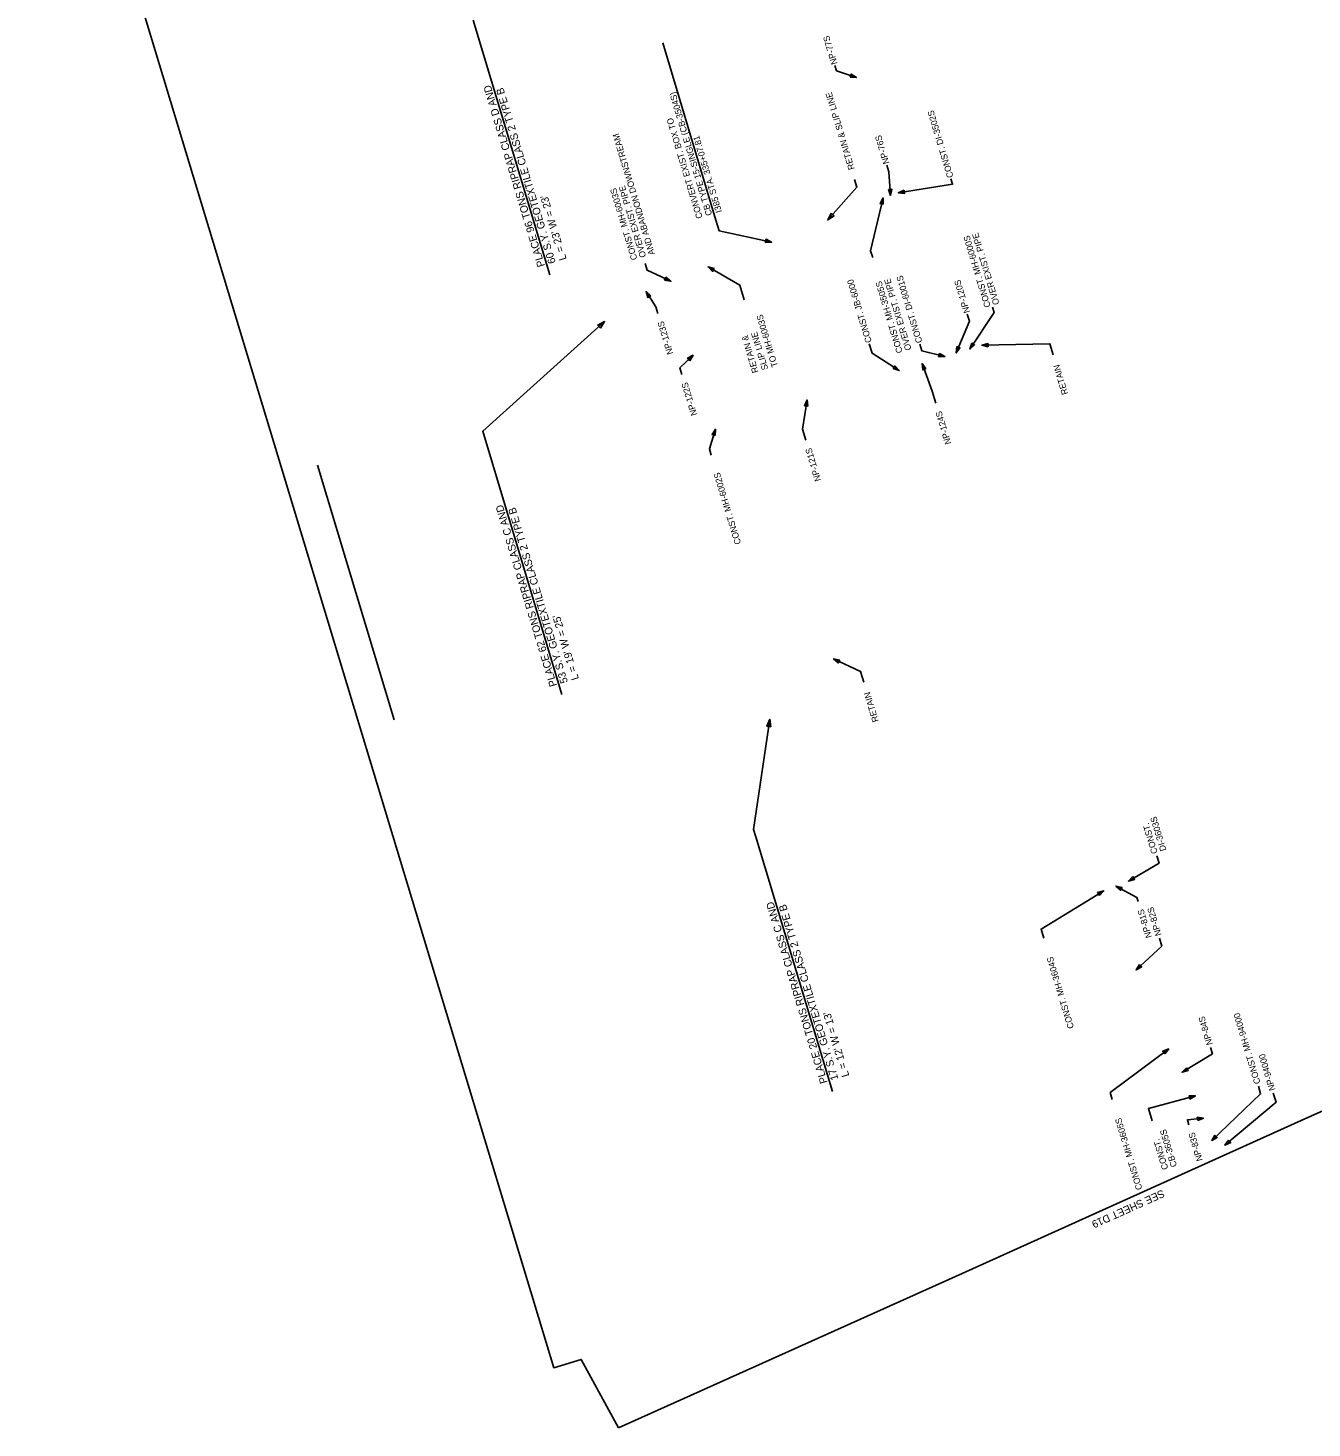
# Model space of a CAD drawing. Extents: x 1612099 to 1613927, y 1087002 to 1088782.
# Drawn here: x 1612109 to 1613125, y 1087002 to 1088109 of the extents above; entities that cross this region are included whole.
import ezdxf

# ---------------------------------------------------------------- set-up
doc = ezdxf.new("R2010")
doc.units = 0
for name, color, linetype in [('BR_CONCRETE', 7, 'Continuous'), ('RD_HY_Area_XP-Post sub TXT', 7, 'Continuous'), ('RD_HY_Misc', 7, 'Continuous')]:
    doc.layers.add(name, color=color, linetype=linetype)

msp = doc.modelspace()

# ---------------------------------------------------------------- linework, layer by layer
at = {"layer": 'BR_CONCRETE'}
for p, q in [((1612461.5, 1088115.6), (1612522, 1087914.2)), ((1612611.5, 1088097.7), (1612653.6, 1087957.4)), ((1612471.1, 1087783.5), (1612531.7, 1087582.1)), ((1612338.3, 1087763.6), (1612398.8, 1087562.2)), ((1612685.2, 1087469.5), (1612745.7, 1087268.1))]:
    msp.add_line(p, q, dxfattribs=at)
for points in [[(1612747.7, 1088079.8), (1612749, 1088075.6), (1612764.8, 1088070.2)], [(1612788.7, 1088001), (1612790.4, 1087995.6), (1612791.8, 1087977)], [(1612763.3, 1087989.7), (1612765.1, 1087983.6), (1612742, 1087957.6)], [(1612839.5, 1087990.1), (1612840.8, 1087985.9), (1612797.9, 1087979.1)], [(1612777.6, 1087927.9), (1612776, 1087933.1), (1612785.8, 1087975)], [(1612653.6, 1087957.4), (1612656.2, 1087949), (1612697.6, 1087940)], [(1612597.5, 1087923.2), (1612599.1, 1087917.9), (1612617.9, 1087909.1)], [(1612676, 1087894.3), (1612672.5, 1087905.9), (1612647.4, 1087920.4)], [(1612607.6, 1087883.7), (1612606, 1087889), (1612598.3, 1087901)], [(1612852.5, 1087883.1), (1612854.2, 1087877.6), (1612843.7, 1087852.4)], [(1612872.4, 1087888.6), (1612873.7, 1087884.3), (1612854.5, 1087855.5)], [(1612471.1, 1087783.5), (1612469, 1087790.4), (1612565.4, 1087877.2)], [(1612774.9, 1087859.6), (1612777.1, 1087852.2), (1612798.6, 1087838.5)], [(1612814.9, 1087859.4), (1612816.5, 1087854.1), (1612834.8, 1087849.5)], [(1612920.4, 1087851), (1612917.8, 1087859.7), (1612864.1, 1087858.5)], [(1612626.7, 1087835.3), (1612625.1, 1087840.6), (1612635.5, 1087850.6)], [(1612827.7, 1087812.6), (1612824.8, 1087822.1), (1612816.7, 1087844)], [(1612724.6, 1087783.4), (1612722, 1087792.1), (1612725.7, 1087815.3)], [(1612649.9, 1087771.5), (1612648.4, 1087776.5), (1612653.1, 1087792.1)], [(1612770.5, 1087592), (1612767.9, 1087600.5), (1612746.6, 1087610.4)], [(1612685.2, 1087469.5), (1612683.4, 1087475.4), (1612696.3, 1087562.6)], [(1613002.4, 1087454.7), (1613004.2, 1087448.8), (1612980, 1087434.6)], [(1612913.1, 1087389.4), (1612910.9, 1087396.7), (1612960.4, 1087426.9)], [(1612987.6, 1087418.4), (1612986.6, 1087421.7), (1612970.1, 1087430.7)], [(1613004.5, 1087389.4), (1613006.3, 1087383.2), (1612986.1, 1087364.4)], [(1612967.2, 1087261.8), (1612965.6, 1087267.3), (1613011.9, 1087301.9)], [(1613045, 1087303), (1613046.5, 1087298), (1613022.4, 1087283.4)], [(1613082.8, 1087272.3), (1613084.6, 1087266.3), (1613045.9, 1087229.4)], [(1612998.8, 1087244.9), (1612995.8, 1087254.8), (1613033, 1087264.7)], [(1613094.6, 1087266.9), (1613096.8, 1087259.7), (1613056.4, 1087225.6)], [(1613027.9, 1087241.9), (1613026.7, 1087245.8), (1613039.4, 1087247)]]:
    msp.add_lwpolyline(points, dxfattribs=at)
for points in [[(1612759.8, 1088070.5), (1612764.8, 1088070.2), (1612760.7, 1088073)], [(1612790.1, 1087981.8), (1612791.8, 1087977), (1612792.7, 1087982)], [(1612802.5, 1087981.2), (1612797.9, 1087979.1), (1612802.9, 1087978.6)], [(1612786, 1087970), (1612785.8, 1087975), (1612783.5, 1087970.6)], [(1612744.7, 1087963), (1612742, 1087957.6), (1612747, 1087960.9)], [(1612692.6, 1087939.7), (1612697.6, 1087940), (1612693.2, 1087942.3)], [(1612652.2, 1087919.1), (1612647.4, 1087920.4), (1612650.9, 1087916.9)], [(1612612.9, 1087909.9), (1612617.9, 1087909.1), (1612614, 1087912.3)], [(1612602, 1087897.6), (1612598.3, 1087901), (1612599.8, 1087896.2)], [(1612562.2, 1087872.1), (1612565.4, 1087877.2), (1612560.1, 1087874.4)], [(1612856.1, 1087860.2), (1612854.5, 1087855.5), (1612858.2, 1087858.8)], [(1612868.9, 1087859.9), (1612864.1, 1087858.5), (1612868.9, 1087857.3)], [(1612632.9, 1087846.3), (1612635.5, 1087850.6), (1612631.1, 1087848.2)], [(1612829.8, 1087849.4), (1612834.8, 1087849.5), (1612830.5, 1087851.9)], [(1612844.3, 1087857.4), (1612843.7, 1087852.4), (1612846.7, 1087856.4)], [(1612793.8, 1087840), (1612798.6, 1087838.5), (1612795.2, 1087842.2)], [(1612819.6, 1087839.9), (1612816.7, 1087844), (1612817.2, 1087839)], [(1612726.3, 1087810.3), (1612725.7, 1087815.3), (1612723.7, 1087810.7)], [(1612653, 1087787.1), (1612653.1, 1087792.1), (1612650.5, 1087787.9)], [(1612751.5, 1087609.5), (1612746.6, 1087610.4), (1612750.4, 1087607.2)], [(1612696.9, 1087556.6), (1612696.3, 1087562.6), (1612693.9, 1087557.1)], [(1612983.5, 1087438.2), (1612980, 1087434.6), (1612984.8, 1087435.9)], [(1612957, 1087423.3), (1612960.4, 1087426.9), (1612955.6, 1087425.5)], [(1612975, 1087429.5), (1612970.1, 1087430.7), (1612973.8, 1087427.3)], [(1612988.8, 1087368.6), (1612986.1, 1087364.4), (1612990.6, 1087366.8)], [(1613008.8, 1087298), (1613011.9, 1087301.9), (1613007.2, 1087300.1)], [(1613025.9, 1087287), (1613022.4, 1087283.4), (1613027.2, 1087284.8)], [(1613028.6, 1087262.2), (1613033, 1087264.7), (1613028, 1087264.7)], [(1613034.8, 1087245.2), (1613039.4, 1087247), (1613034.5, 1087247.8)], [(1613048.5, 1087233.7), (1613045.9, 1087229.4), (1613050.3, 1087231.8)], [(1613059.2, 1087229.7), (1613056.4, 1087225.6), (1613060.9, 1087227.7)]]:
    msp.add_lwpolyline(points, close=True, dxfattribs=at)
at = {"layer": 'RD_HY_Misc'}
msp.add_lwpolyline([(1612576.5, 1087002), (1612843.1, 1087121.9), (1613116.7, 1087245.1), (1613415.2, 1087379), (1613026.4, 1088673.8), (1612864.6, 1088666.6), (1612609.2, 1088638), (1612610.6, 1088625.9), (1612401.2, 1088591.8), (1612109.2, 1088544.3), (1612170.2, 1088342.4), (1612137.1, 1088332.4), (1612525.2, 1087049.6), (1612547, 1087056.2)], close=True, dxfattribs=at)
msp.add_lwpolyline([(1612576.5, 1087002), (1612843.1, 1087121.9), (1613116.7, 1087245.1), (1613415.2, 1087379), (1613026.4, 1088673.8), (1612864.6, 1088666.6), (1612609.2, 1088638), (1612610.6, 1088625.9), (1612401.2, 1088591.8), (1612109.2, 1088544.3), (1612170.2, 1088342.4), (1612137.1, 1088332.4), (1612525.2, 1087049.6), (1612547, 1087056.2)], close=True, dxfattribs=at)
msp.add_lwpolyline([(1612576.5, 1087002), (1612843.1, 1087121.9), (1613116.7, 1087245.1), (1613415.2, 1087379), (1613026.4, 1088673.8), (1612864.6, 1088666.6), (1612609.2, 1088638), (1612610.6, 1088625.9), (1612401.2, 1088591.8), (1612109.2, 1088544.3), (1612170.2, 1088342.4), (1612137.1, 1088332.4), (1612525.2, 1087049.6), (1612547, 1087056.2)], close=True, dxfattribs=at)
msp.add_lwpolyline([(1612576.5, 1087002), (1612843.1, 1087121.9), (1613116.7, 1087245.1), (1613415.2, 1087379), (1613026.4, 1088673.8), (1612864.6, 1088666.6), (1612609.2, 1088638), (1612610.6, 1088625.9), (1612401.2, 1088591.8), (1612109.2, 1088544.3), (1612170.2, 1088342.4), (1612137.1, 1088332.4), (1612525.2, 1087049.6), (1612547, 1087056.2)], close=True, dxfattribs=at)
msp.add_lwpolyline([(1612576.5, 1087002), (1612843.1, 1087121.9), (1613116.7, 1087245.1), (1613415.2, 1087379), (1613026.4, 1088673.8), (1612864.6, 1088666.6), (1612609.2, 1088638), (1612610.6, 1088625.9), (1612401.2, 1088591.8), (1612109.2, 1088544.3), (1612170.2, 1088342.4), (1612137.1, 1088332.4), (1612525.2, 1087049.6), (1612547, 1087056.2)], close=True, dxfattribs=at)
msp.add_lwpolyline([(1612576.5, 1087002), (1612843.1, 1087121.9), (1613116.7, 1087245.1), (1613415.2, 1087379), (1613026.4, 1088673.8), (1612864.6, 1088666.6), (1612609.2, 1088638), (1612610.6, 1088625.9), (1612401.2, 1088591.8), (1612109.2, 1088544.3), (1612170.2, 1088342.4), (1612137.1, 1088332.4), (1612525.2, 1087049.6), (1612547, 1087056.2)], close=True, dxfattribs=at)
msp.add_lwpolyline([(1612576.5, 1087002), (1612843.1, 1087121.9), (1613116.7, 1087245.1), (1613415.2, 1087379), (1613026.4, 1088673.8), (1612864.6, 1088666.6), (1612609.2, 1088638), (1612610.6, 1088625.9), (1612401.2, 1088591.8), (1612109.2, 1088544.3), (1612170.2, 1088342.4), (1612137.1, 1088332.4), (1612525.2, 1087049.6), (1612547, 1087056.2)], close=True, dxfattribs=at)
msp.add_lwpolyline([(1612576.5, 1087002), (1612843.1, 1087121.9), (1613116.7, 1087245.1), (1613415.2, 1087379), (1613026.4, 1088673.8), (1612864.6, 1088666.6), (1612609.2, 1088638), (1612610.6, 1088625.9), (1612401.2, 1088591.8), (1612109.2, 1088544.3), (1612170.2, 1088342.4), (1612137.1, 1088332.4), (1612525.2, 1087049.6), (1612547, 1087056.2)], close=True, dxfattribs=at)
msp.add_lwpolyline([(1612576.5, 1087002), (1612843.1, 1087121.9), (1613116.7, 1087245.1), (1613415.2, 1087379), (1613026.4, 1088673.8), (1612864.6, 1088666.6), (1612609.2, 1088638), (1612610.6, 1088625.9), (1612401.2, 1088591.8), (1612109.2, 1088544.3), (1612170.2, 1088342.4), (1612137.1, 1088332.4), (1612525.2, 1087049.6), (1612547, 1087056.2)], close=True, dxfattribs=at)

# ---------------------------------------------------------------- texts
at = {"layer": 'BR_CONCRETE'}
for s, height, p in [('NP-77S', 5, (1612749.8, 1088081.4)), ('PLACE 96 TONS RIPRAP CLASS D AND', 6, (1612518.3, 1087921.4)), ('60 S.Y. GEOTEXTILE CLASS 2 TYPE B', 6, (1612526.9, 1087924)), ('CB TYPE 15-SINGLE (CB-3504S)', 5, (1612650.7, 1087961.8)), ('RETAIN & SLIP LINE', 5, (1612763.4, 1087998.1)), ('CONVERT EXIST. BOX TO', 5, (1612643.1, 1087959.5)), ('CONST. DI-3502S', 5, (1612841.6, 1087991.8)), ('AND ABANDON DOWNSTREAM', 5, (1612605.3, 1087930.8)), ('I385 STA. 335+07.81', 5, (1612658.4, 1087964.1)), ('NP-76S', 5, (1612790.9, 1088002.7)), ('CONST. MH-6003S', 5, (1612591.5, 1087926.7)), ('OVER EXIST. PIPE', 5, (1612598.4, 1087928.7)), ("L = 23' W = 23'", 6, (1612535.5, 1087926.6)), ('OVER EXIST. PIPE', 5, (1612878, 1087891.3)), ('CONST. MH-6000S', 5, (1612871.1, 1087889.2)), ('CONST. DI-6001S', 5, (1612817, 1087861.1)), ('CONST. JB-6000', 5, (1612777, 1087861.3)), ('CONST. MH-3505S', 5, (1612801.5, 1087853.1)), ('OVER EXIST. PIPE', 5, (1612808.4, 1087855.2)), ('NP-120S', 5, (1612854.6, 1087884.8)), ('TO MH-6003S', 5, (1612702.7, 1087842)), ('NP-123S', 5, (1612619.8, 1087852)), ('SLIP LINE', 5, (1612695, 1087839.7)), ('RETAIN & ', 5, (1612687.3, 1087837.4)), ('RETAIN', 5, (1612932.3, 1087820.2)), ('NP-122S', 5, (1612638.8, 1087803.6)), ('NP-124S', 5, (1612839.8, 1087780.9)), ('NP-121S', 5, (1612736.8, 1087751.7)), ('CONST. MH-6002S', 5, (1612673.5, 1087701.7)), ('PLACE 62 TONS RIPRAP CLASS C AND', 6, (1612527.9, 1087589.4)), ('53 S.Y. GEOTEXTILE CLASS 2 TYPE B', 6, (1612536.5, 1087592)), ("L = 19' W = 25'", 6, (1612545.2, 1087594.6)), ('RETAIN', 5, (1612782.4, 1087561.2)), ('DI-3603S', 5, (1613010.1, 1087459.1)), ('CONST.', 5, (1613003.2, 1087457)), ('PLACE 20 TONS RIPRAP CLASS C AND', 6, (1612742, 1087275.4)), ('17 S.Y. GEOTEXTILE CLASS 2 TYPE B', 6, (1612750.6, 1087278)), ('NP-81S', 5, (1612998.6, 1087390.4)), ('NP-82S', 5, (1613006.3, 1087392.1)), ('CONST. MH-3604S', 5, (1612937, 1087318.7)), ("L = 12' W = 13'", 6, (1612759.2, 1087280.6)), ('NP-84S', 5, (1613046.8, 1087305.7)), ('CONST. MH-94000', 5, (1613084.6, 1087274.9)), ('NP-94000', 5, (1613096.4, 1087269.6)), ('CONST. MH-3605S', 5, (1612991.1, 1087191.1)), ('CB-3605S', 5, (1613018.5, 1087209.2)), ('CONST.', 5, (1613011.6, 1087207.1)), ('NP-83S', 5, (1613038.9, 1087213.9))]:
    msp.add_text(s, height=height, rotation=106.7335, dxfattribs=at).set_placement(p)
at = {"layer": 'RD_HY_Area_XP-Post sub TXT'}
msp.add_text('SEE SHEET D19', height=6, rotation=204.2335, dxfattribs=at).set_placement((1613006.9, 1087190.7))

doc.saveas('drawing.dxf')
